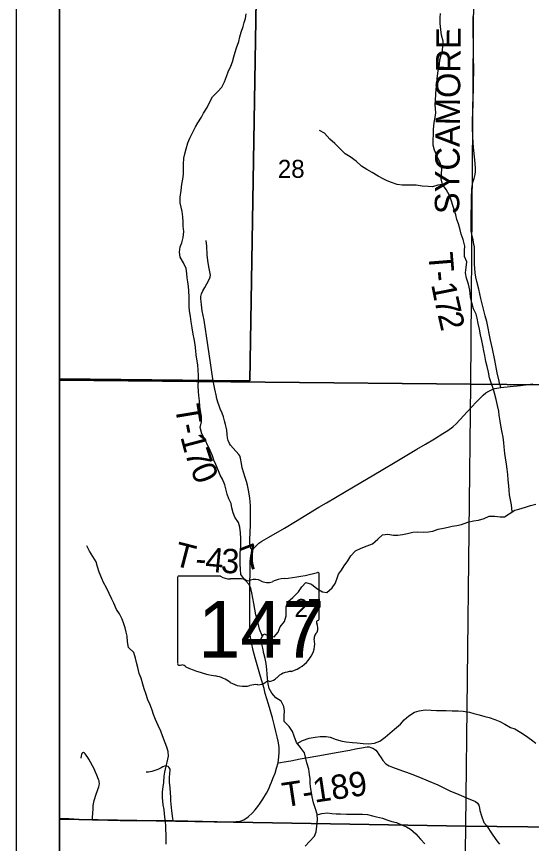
# Model space of a CAD drawing. Extents: x 0 to 34, y -8.9 to 22.
# Drawn here: x 23.617 to 24.815, y 8.187 to 10.111 of the extents above; entities that cross this region are included whole.
import ezdxf

# ---------------------------------------------------------------- set-up
doc = ezdxf.new("R2010")
doc.units = 0
for name, color, linetype in [('GM_X_Corporation', 7, 'Continuous'), ('GM_X_Minor_River', 7, 'Continuous'), ('GM_X_Section_Text', 7, 'Continuous'), ('GM_X_State_Location', 7, 'Continuous'), ('GM_X_State_Route', 7, 'Continuous'), ('GM_X_State_Shield', 7, 'Continuous'), ('GM_X_Township_Road', 7, 'Continuous'), ('GM_X_Township_Road_Text', 7, 'Continuous'), ('SH_Data', 7, 'Continuous')]:
    doc.layers.add(name, color=color, linetype=linetype)

msp = doc.modelspace()

# ---------------------------------------------------------------- linework, layer by layer
at = {"layer": 'GM_X_Corporation'}
for points in [[(23.7167, 11.9654), (23.7167, 7.104), (28.7046, 7.104), (28.7123, 8.2818), (28.7238, 9.1729), (28.7308, 9.4444), (28.7377, 10.2012)], [(24.1844, 10.755), (24.1596, 9.2636), (24.0743, 9.2644), (23.7167, 9.2682), (23.7167, 7.104), (28.7046, 7.104), (28.7123, 8.2818), (28.7238, 9.1729), (28.7308, 9.4444), (28.7377, 10.2012)]]:
    msp.add_lwpolyline(points, dxfattribs=at)
for points in [[(23.7167, 11.9654), (23.7167, 9.2682), (24.0743, 9.2644), (24.1596, 9.2636), (24.1844, 10.755), (24.1845, 10.7587), (24.2007, 11.7362), (24.2025, 11.824), (24.2028, 11.8378), (24.2054, 11.9625), (24.1849, 11.9621)], [(23.7167, 10.2843), (23.7167, 9.2652), (24.6733, 9.2562), (24.6816, 10.2678)], [(24.6816, 10.2678), (25.698, 10.2614), (25.683, 9.2467), (24.6733, 9.2562)], [(23.7167, 9.2652), (23.7167, 8.2443), (24.6618, 8.2279), (24.6733, 9.2562)], [(25.683, 9.2467), (25.6692, 8.2169), (24.6618, 8.2279), (24.6733, 9.2562)], [(23.7167, 8.2443), (23.7167, 7.2154), (24.6491, 7.2004), (24.6618, 8.2279)], [(24.6618, 8.2279), (25.6692, 8.2169), (25.6523, 7.1969), (24.6491, 7.2004)]]:
    msp.add_lwpolyline(points, close=True, dxfattribs=at)
at = {"layer": 'GM_X_Minor_River'}
for points in [[(24.0515, 9.8863), (24.0602, 9.9), (24.067, 9.9141), (24.0723, 9.9244), (24.0852, 9.937), (24.0942, 9.9473), (24.1003, 9.959), (24.1048, 9.972), (24.109, 9.9826), (24.1154, 9.9956), (24.1191, 10.0062), (24.1222, 10.0176), (24.1252, 10.0283), (24.1286, 10.0381), (24.1335, 10.053), (24.1361, 10.064), (24.1391, 10.0746), (24.1436, 10.0879), (24.1466, 10.0975), (24.1493, 10.107), (24.1511, 10.1172)], [(24.7698, 8.9588), (24.7678, 8.9756), (24.7658, 8.9866), (24.7639, 8.9983), (24.7628, 9.0094), (24.762, 9.0196), (24.7608, 9.0336), (24.7596, 9.0458), (24.7581, 9.0579), (24.7569, 9.0697), (24.7542, 9.0849), (24.7527, 9.0947), (24.7508, 9.1099), (24.7504, 9.1198), (24.7488, 9.1327), (24.7461, 9.1433), (24.7434, 9.16), (24.7419, 9.1699), (24.7396, 9.1835), (24.7384, 9.1934), (24.7357, 9.2067), (24.7323, 9.2207), (24.7285, 9.2348), (24.7254, 9.2461), (24.7208, 9.2594), (24.717, 9.2704), (24.7143, 9.2841), (24.7116, 9.2974), (24.7086, 9.3087), (24.7063, 9.3224), (24.704, 9.3338), (24.7013, 9.3463), (24.6993, 9.3577), (24.6963, 9.371), (24.6936, 9.3839), (24.6909, 9.3971), (24.6886, 9.4097), (24.6859, 9.4191), (24.6798, 9.4313), (24.6756, 9.4449), (24.6729, 9.4593), (24.671, 9.4745), (24.6683, 9.4886), (24.6637, 9.5022), (24.6614, 9.5147), (24.6629, 9.5277), (24.6644, 9.5406), (24.659, 9.5531), (24.659, 9.5671), (24.6597, 9.5774), (24.6559, 9.5926), (24.6513, 9.6051), (24.6487, 9.615), (24.6445, 9.629), (24.641, 9.6392), (24.6383, 9.6499), (24.6353, 9.6597), (24.6314, 9.6719), (24.6284, 9.6821), (24.6238, 9.6946), (24.6162, 9.7086), (24.6078, 9.7204), (24.6047, 9.7333), (24.6055, 9.7451), (24.6058, 9.7572), (24.6024, 9.7709), (24.5951, 9.786), (24.589, 9.8001), (24.5863, 9.8122), (24.5859, 9.8228), (24.5867, 9.838), (24.587, 9.8487), (24.5885, 9.8646), (24.5907, 9.8764), (24.5919, 9.887), (24.5914, 9.8965), (24.5907, 9.9068), (24.591, 9.917), (24.5921, 9.9307), (24.5929, 9.9425), (24.5947, 9.9546), (24.5955, 9.9664), (24.5969, 9.9797), (24.5984, 9.9896), (24.6003, 9.9999), (24.6018, 10.0109), (24.6044, 10.0219), (24.6074, 10.0314), (24.6086, 10.0436), (24.6093, 10.0538), (24.6055, 10.0682), (24.6035, 10.0811), (24.602, 10.0948), (24.6019, 10.1089), (24.6031, 10.1184)], [(24.1887, 8.6691), (24.1818, 8.6862), (24.1787, 8.6998), (24.1764, 8.7093), (24.1737, 8.7196), (24.1707, 8.7325), (24.1684, 8.7457), (24.1664, 8.7583), (24.1637, 8.7704), (24.1614, 8.7803), (24.1576, 8.7897), (24.1477, 8.8011), (24.1382, 8.8132), (24.1374, 8.8254), (24.137, 8.8371), (24.1366, 8.8508), (24.137, 8.8637), (24.1381, 8.877), (24.1384, 8.8876), (24.1384, 8.8971), (24.138, 8.9104), (24.1361, 8.9233), (24.133, 8.9343), (24.1246, 8.9468), (24.1204, 8.9567), (24.1178, 8.9684), (24.1158, 8.9787), (24.1109, 8.9889), (24.1063, 9.0003), (24.1036, 9.0124), (24.1009, 9.0219), (24.0956, 9.0348), (24.0903, 9.0446), (24.0868, 9.0545), (24.0807, 9.0689), (24.0754, 9.0791), (24.0723, 9.0894), (24.067, 9.1019), (24.059, 9.1178), (24.0548, 9.1273), (24.0476, 9.1402), (24.0441, 9.1554), (24.0467, 9.1687), (24.0467, 9.1819), (24.0448, 9.1941), (24.0432, 9.2043), (24.0424, 9.2169), (24.0409, 9.2298), (24.0397, 9.2392), (24.039, 9.2518), (24.0397, 9.2639), (24.04, 9.2753), (24.0392, 9.2894), (24.0381, 9.3), (24.0346, 9.3239), (24.0335, 9.3334), (24.0319, 9.3482), (24.03, 9.3611), (24.0277, 9.3725), (24.0254, 9.3869), (24.0231, 9.4009), (24.0211, 9.4135), (24.0188, 9.4267), (24.018, 9.4366), (24.0184, 9.448), (24.018, 9.4586), (24.0176, 9.4734), (24.0164, 9.4829), (24.0149, 9.4939), (24.0133, 9.5034), (24.0125, 9.5137), (24.011, 9.5251), (24.0049, 9.538), (23.9977, 9.5516), (23.9961, 9.563), (23.9972, 9.5751), (24.001, 9.585), (24.004, 9.5972), (24.0059, 9.6109), (24.0043, 9.6238), (24.0043, 9.634), (24.0039, 9.645), (24.0023, 9.6576), (23.9997, 9.6674), (23.9977, 9.6781), (23.9973, 9.691), (24, 9.7062), (24.0014, 9.721), (24.0033, 9.7328), (24.0052, 9.7445), (24.0051, 9.7681), (24.0062, 9.7821), (24.0085, 9.7916), (24.0111, 9.8038), (24.0149, 9.8171), (24.0202, 9.8285), (24.0273, 9.8441), (24.033, 9.8544), (24.0387, 9.8639), (24.047, 9.8768), (24.0515, 9.8863)], [(24.6078, 9.7204), (24.5968, 9.7192), (24.5847, 9.7154), (24.5744, 9.7161), (24.56, 9.7168), (24.5463, 9.7187), (24.5334, 9.719), (24.5236, 9.7186), (24.5141, 9.7193), (24.5019, 9.7208), (24.489, 9.7249), (24.4791, 9.7291), (24.4693, 9.734), (24.4579, 9.74), (24.4438, 9.7483), (24.432, 9.7551), (24.4191, 9.7634), (24.4066, 9.7751), (24.3929, 9.7846), (24.3815, 9.7921), (24.3697, 9.8035), (24.3568, 9.8156), (24.3457, 9.8262), (24.3332, 9.8402), (24.3214, 9.8459)], [(24.2163, 8.6685), (24.225, 8.6791), (24.2299, 8.6917), (24.2402, 8.7039), (24.2443, 8.7168), (24.2443, 8.7377), (24.248, 8.7498), (24.2598, 8.7593), (24.273, 8.7727), (24.2802, 8.7845), (24.29, 8.7944), (24.303, 8.7906), (24.3155, 8.7804), (24.3284, 8.7729), (24.3383, 8.7714), (24.3508, 8.7821), (24.3576, 8.792), (24.3621, 8.8022), (24.3655, 8.8136), (24.3727, 8.8235), (24.3788, 8.833), (24.3871, 8.8452), (24.3943, 8.857), (24.4052, 8.8684), (24.4181, 8.8745), (24.4322, 8.8799), (24.4447, 8.8849), (24.4572, 8.8952), (24.4681, 8.9051), (24.4807, 8.9074), (24.494, 8.9044), (24.5038, 8.9048), (24.5148, 8.9064), (24.5262, 8.9083), (24.5387, 8.9118), (24.5505, 8.9122), (24.5641, 8.9115), (24.5748, 8.9123), (24.585, 8.9142), (24.5975, 8.9184), (24.61, 8.9211), (24.621, 8.9231), (24.6305, 8.9254), (24.6411, 8.9273), (24.6518, 8.9296), (24.6665, 8.935), (24.6798, 8.9381), (24.6916, 8.9396), (24.7045, 8.9435), (24.7162, 8.9492), (24.7291, 8.9489), (24.742, 8.947), (24.7519, 8.9474), (24.7625, 8.9543), (24.7761, 8.9627), (24.7856, 8.9654), (24.8004, 8.9696), (24.8125, 8.9738), (24.8251, 8.9769)], [(23.9647, 8.1855), (23.9646, 8.2094), (23.9642, 8.2193), (23.9642, 8.2299), (23.9627, 8.2424), (23.9607, 8.2561), (23.9603, 8.2663), (23.958, 8.2773), (23.9565, 8.2944), (23.9565, 8.3077), (23.9579, 8.3191), (23.9591, 8.329), (23.9605, 8.3438), (23.962, 8.3533), (23.9647, 8.3673), (23.9669, 8.3768), (23.9699, 8.3905), (23.9695, 8.4015), (23.9665, 8.4117), (23.9623, 8.4212), (23.9562, 8.4375), (23.9523, 8.4485), (23.9462, 8.4622), (23.9398, 8.4758), (23.9356, 8.4872), (23.9325, 8.4974), (23.9272, 8.5103), (23.9222, 8.5217), (23.9176, 8.5361), (23.9138, 8.5471), (23.9107, 8.5577), (23.9069, 8.5717), (23.9016, 8.5831), (23.8985, 8.5968), (23.8958, 8.6085), (23.8935, 8.6188), (23.8893, 8.632), (23.8768, 8.6434), (23.8745, 8.6567), (23.8741, 8.6696), (23.8721, 8.6794), (23.8695, 8.6889), (23.8664, 8.6984), (23.8626, 8.7094), (23.8565, 8.7219), (23.8489, 8.7321), (23.8432, 8.7462), (23.8382, 8.7556), (23.8325, 8.7689), (23.826, 8.7818), (23.8191, 8.7947), (23.815, 8.8042), (23.8089, 8.8186), (23.805, 8.8307), (23.8016, 8.8428), (23.7943, 8.855), (23.7867, 8.8675), (23.7799, 8.88)], [(24.288, 8.1813), (24.2986, 8.1919), (24.31, 8.2045), (24.3141, 8.2148), (24.3156, 8.2277), (24.3171, 8.2421), (24.3159, 8.2554), (24.3121, 8.2679), (24.3075, 8.2823), (24.3048, 8.2956), (24.3025, 8.3062), (24.3006, 8.3191), (24.2998, 8.3286), (24.2994, 8.3381), (24.2986, 8.3476), (24.2963, 8.3605), (24.2921, 8.3749), (24.2894, 8.3851), (24.2864, 8.3984), (24.2772, 8.4109), (24.2677, 8.4223), (24.2628, 8.4374), (24.259, 8.4477), (24.2513, 8.4598), (24.2395, 8.4715), (24.2395, 8.484), (24.2399, 8.4962), (24.2387, 8.5064), (24.2326, 8.5182), (24.2201, 8.5265), (24.2109, 8.5371), (24.2045, 8.5481), (24.2018, 8.5591), (24.2002, 8.5716), (24.1995, 8.5811), (24.1987, 8.5921), (24.1971, 8.6058), (24.1952, 8.6175), (24.1921, 8.6297), (24.1895, 8.6418), (24.1872, 8.6513), (24.186, 8.6642), (24.192, 8.6752), (24.2046, 8.6703), (24.2163, 8.6685)], [(24.2696, 8.42), (24.2821, 8.4272), (24.2973, 8.4326), (24.3117, 8.4349), (24.3227, 8.4361), (24.3368, 8.4362), (24.3463, 8.4347), (24.3603, 8.4294), (24.3744, 8.4253), (24.3838, 8.4238), (24.3986, 8.4223), (24.4093, 8.4212), (24.4233, 8.4198), (24.4362, 8.4194), (24.4491, 8.421), (24.462, 8.4252), (24.4745, 8.4344), (24.4851, 8.4443), (24.4957, 8.453), (24.5097, 8.4652), (24.5181, 8.4747), (24.529, 8.4847), (24.5423, 8.4931), (24.5537, 8.4961), (24.5673, 8.4981), (24.581, 8.4977), (24.5939, 8.497), (24.6049, 8.4967), (24.6159, 8.4967), (24.63, 8.4964), (24.644, 8.4961), (24.6558, 8.495), (24.6702, 8.4927), (24.6808, 8.4901), (24.6926, 8.4864), (24.7063, 8.4826), (24.7161, 8.4804), (24.7294, 8.4755), (24.7412, 8.471), (24.753, 8.4653), (24.7655, 8.457), (24.7761, 8.454), (24.7902, 8.4453), (24.8008, 8.4385), (24.8145, 8.4287), (24.8248, 8.4211)], [(24.3161, 8.2538), (24.3269, 8.2573), (24.3398, 8.2585), (24.3504, 8.2574), (24.3599, 8.2567), (24.3702, 8.2563), (24.3842, 8.2556), (24.3952, 8.2553), (24.4085, 8.2557), (24.4218, 8.2558), (24.4328, 8.2547), (24.4446, 8.2517), (24.4544, 8.2498), (24.4677, 8.2464), (24.478, 8.2427), (24.4897, 8.2389), (24.5008, 8.2359), (24.5106, 8.2318), (24.5239, 8.2265), (24.5334, 8.2205), (24.546, 8.2099), (24.5562, 8.1978), (24.5665, 8.1868)]]:
    msp.add_lwpolyline(points, dxfattribs=at)
at = {"layer": 'GM_X_State_Route'}
for points in [[(23.784, 8.2432), (23.7935, 8.2426), (23.8063, 8.2423), (23.8292, 8.2416), (23.8577, 8.2412), (23.8961, 8.2409), (23.9255, 8.2409), (23.9612, 8.2407), (23.9808, 8.2406), (24.0833, 8.2385), (24.1176, 8.2378), (24.128, 8.2386), (24.1369, 8.2396), (24.1456, 8.2428), (24.1557, 8.2494), (24.1659, 8.2589), (24.1716, 8.2656), (24.1781, 8.2738), (24.1837, 8.2816), (24.19, 8.2907), (24.1983, 8.3046), (24.2034, 8.3148), (24.2069, 8.3229), (24.21, 8.3299), (24.2133, 8.3388), (24.2181, 8.3511), (24.2217, 8.3623), (24.2252, 8.3751), (24.2265, 8.3892), (24.2274, 8.3987), (24.2273, 8.4096), (24.2267, 8.4169), (24.2254, 8.4254), (24.2232, 8.4357), (24.2199, 8.4481), (24.2168, 8.461), (24.2118, 8.4797), (24.2025, 8.5118), (24.1953, 8.5367), (24.1924, 8.5481), (24.184, 8.5756), (24.1719, 8.6195), (24.1674, 8.6365), (24.163, 8.6551), (24.1608, 8.6668), (24.1601, 8.6742), (24.1595, 8.6878), (24.1591, 8.6994), (24.1591, 8.721), (24.1598, 8.7806), (24.1601, 8.8297), (24.1604, 8.8443), (24.1609, 8.85), (24.1619, 8.857), (24.163, 8.8621), (24.1659, 8.8695), (24.1691, 8.8746), (24.1757, 8.8816), (24.1805, 8.8858), (24.1875, 8.8908), (24.2034, 8.9004), (24.2398, 8.9213), (24.2655, 8.9368), (24.3202, 8.9696), (24.338, 8.9801), (24.4007, 9.017), (24.4646, 9.055), (24.5015, 9.0771), (24.5477, 9.1044), (24.5681, 9.1165), (24.5887, 9.1286), (24.6085, 9.1409), (24.6202, 9.1484), (24.6314, 9.1565), (24.6402, 9.1644), (24.6567, 9.1824), (24.676, 9.2036), (24.6861, 9.2142), (24.7025, 9.2305), (24.7088, 9.2355), (24.7156, 9.2398), (24.7232, 9.2438), (24.7297, 9.2456), (24.7434, 9.2485), (24.7647, 9.2505), (24.7888, 9.2532), (24.8178, 9.2564)], [(23.7167, 8.2467), (23.7385, 8.2457), (23.7622, 8.2443), (23.7803, 8.2435), (23.784, 8.2432)]]:
    msp.add_lwpolyline(points, dxfattribs=at)
at = {"layer": 'GM_X_State_Shield'}
for p, q in [((24.3208, 8.7096), (24.3208, 8.8143)), ((23.9912, 8.8059), (23.9912, 8.6058)), ((24.091, 8.8093), (23.9945, 8.8093)), ((24.3208, 8.7096), (24.3208, 8.7096))]:
    msp.add_line(p, q, dxfattribs=at)
for centre, major_axis, start_param, end_param in [((24.2034, 9.0822), (0.3495, 0), 4.814394, 5.042369), ((24.3172, 8.8147), (0.00367, 0), 6.141152, 7.989035), ((23.995, 8.8063), (0.00382, 0), 1.712693, 3.28349), ((24.114, 8.8326), (0.037, 0), 4.042523, 4.731795), ((24.1263, 8.697), (0.133, 0), 1.404758, 1.657858), ((24.1564, 8.8073), (0.0107, 0), 3.836095, 5.185415), ((24.1721, 8.7842), (0.0222, 0), 0.950623, 2.079405), ((24.2008, 8.8159), (0.0267, 0), 4.081561, 5.145723), ((24.248, 8.7482), (0.0703, 0), 1.699011, 2.107814), ((24.32, 8.7019), (0.00568, 0), 1.883978, 3.671073), ((24.2838, 8.6887), (0.0341, 0), 5.934695, 6.695948), ((24.3169, 8.7092), (0.00393, 0), 5.05454, 6.418171), ((24.334, 8.6658), (0.0248, 0), 2.387724, 3.262537), ((24.223, 8.6525), (0.0874, 0), 5.101752, 6.440018), ((23.995, 8.6053), (0.00385, 0), 3.00124, 4.508301), ((23.9956, 8.6258), (0.0294, 0), 4.665946, 4.897461), ((24.0016, 8.5942), (0.0106, 0), 0.519207, 1.627899), ((24.1355, 8.774), (0.2524, 0), 4.195997, 4.488961), ((24.2599, 8.5496), (0.0479, 0), 1.647645, 2.488434), ((24.0602, 8.5159), (0.079, 0), 0.823519, 1.323587), ((24.1456, 8.5932), (0.0501, 0), 4.026481, 4.996735), ((24.1782, 8.5782), (0.0267, 0), 4.691044, 5.507374), ((24.2024, 8.5589), (0.00752, 0), 1.147584, 2.315152), ((24.1992, 8.5864), (0.0282, 0), 4.937069, 5.64225), ((24.1746, 8.524), (0.0412, 0), 1.495662, 1.94098)]:
    msp.add_ellipse(centre, major_axis=major_axis, ratio=0.8, start_param=start_param, end_param=end_param, dxfattribs=at)
at = {"layer": 'GM_X_Township_Road'}
for points in [[(24.7434, 9.2485), (24.7415, 9.2539), (24.7403, 9.2578), (24.7391, 9.2632), (24.7351, 9.2825), (24.7294, 9.3121), (24.724, 9.3385), (24.7197, 9.3587), (24.7106, 9.4017), (24.7069, 9.4153), (24.697, 9.4549), (24.6918, 9.4772), (24.6873, 9.4946), (24.6851, 9.5051), (24.6835, 9.5147), (24.6823, 9.5349), (24.6822, 9.5589), (24.6818, 9.5708), (24.6818, 9.5756), (24.6807, 9.5806), (24.6789, 9.5915), (24.6767, 9.6005), (24.6745, 9.6126), (24.6743, 9.6221), (24.6743, 9.6338), (24.6742, 9.6527), (24.675, 9.6712), (24.6755, 9.695), (24.6757, 9.7042), (24.6762, 9.7106), (24.6768, 9.7163), (24.6777, 9.7216), (24.6792, 9.7284), (24.6812, 9.7346), (24.684, 9.7437), (24.6846, 9.7509), (24.6847, 9.7575), (24.684, 9.7695), (24.6832, 9.7775), (24.6801, 9.8064), (24.6779, 9.8306), (24.6776, 9.8541), (24.6774, 9.8699), (24.679, 9.9065), (24.6798, 9.9573), (24.6803, 9.9865), (24.6801, 10.018), (24.6795, 10.0496), (24.6789, 10.0718), (24.6789, 10.0835), (24.6788, 10.0987), (24.6793, 10.1082), (24.6799, 10.116)], [(24.0815, 9.2274), (24.0777, 9.2446), (24.0745, 9.2638), (24.0714, 9.2839), (24.0678, 9.3058), (24.0649, 9.3268), (24.062, 9.3477), (24.0531, 9.4048), (24.0488, 9.4266), (24.0466, 9.4407), (24.046, 9.4483), (24.0456, 9.4543), (24.0458, 9.4596), (24.0464, 9.4633), (24.0472, 9.4663), (24.0504, 9.4728), (24.0547, 9.4807), (24.0644, 9.498), (24.0665, 9.5033), (24.0672, 9.5059), (24.0677, 9.5094), (24.0644, 9.5289), (24.062, 9.544), (24.0603, 9.5571), (24.0594, 9.5773), (24.0582, 9.5899)], [(24.1659, 8.8695), (24.162, 8.8737), (24.1605, 8.8803), (24.1596, 8.886), (24.1595, 8.8949), (24.1606, 8.9282), (24.1609, 8.9496), (24.1609, 8.9726), (24.1592, 8.9919), (24.1565, 9.0094), (24.1542, 9.0209), (24.1515, 9.0297), (24.1477, 9.0411), (24.1453, 9.0488), (24.1417, 9.0615), (24.14, 9.0716), (24.1378, 9.0838), (24.1359, 9.0892), (24.134, 9.0927), (24.1205, 9.1071), (24.1148, 9.1138), (24.112, 9.1183), (24.1089, 9.125), (24.1075, 9.1313), (24.1064, 9.1386), (24.1056, 9.1488), (24.1042, 9.1559), (24.103, 9.1621), (24.1005, 9.1708), (24.0979, 9.1798), (24.0947, 9.1887), (24.0904, 9.1985), (24.0878, 9.2052), (24.0846, 9.2142), (24.0819, 9.2253), (24.0815, 9.2274)], [(24.2252, 8.3751), (24.2308, 8.3758), (24.2391, 8.3771), (24.2546, 8.3799), (24.2767, 8.3844), (24.295, 8.3878), (24.3178, 8.3915), (24.3391, 8.3952), (24.3601, 8.399), (24.3923, 8.4049), (24.4051, 8.4073), (24.419, 8.4103), (24.4327, 8.412), (24.4368, 8.412), (24.4413, 8.4108), (24.4454, 8.4095), (24.4495, 8.4071), (24.4527, 8.4045), (24.4559, 8.4004), (24.4595, 8.3946), (24.4649, 8.3863), (24.4691, 8.3801), (24.4762, 8.3729), (24.4837, 8.3683), (24.4913, 8.365), (24.4977, 8.3624), (24.5081, 8.3587), (24.5148, 8.3563), (24.5241, 8.353), (24.5361, 8.3488), (24.5543, 8.3418), (24.5743, 8.3332), (24.5969, 8.3235), (24.6246, 8.3102), (24.6454, 8.3013), (24.6689, 8.2916), (24.6791, 8.2875), (24.6843, 8.2853), (24.6889, 8.2814), (24.6921, 8.2763), (24.6934, 8.2699), (24.6942, 8.264), (24.698, 8.2514), (24.7041, 8.2364), (24.71, 8.2296), (24.7233, 8.2088), (24.73, 8.1989), (24.736, 8.1907), (24.7402, 8.1858)], [(23.7935, 8.2426), (23.7934, 8.2474), (23.7942, 8.2589), (23.7946, 8.2672), (23.7952, 8.2759), (23.7972, 8.2875), (23.8021, 8.3023), (23.805, 8.3106), (23.8067, 8.3153), (23.8081, 8.3192), (23.8088, 8.3227), (23.8094, 8.3269), (23.8092, 8.3297), (23.8087, 8.3333), (23.8077, 8.336), (23.8031, 8.3465), (23.8004, 8.3533), (23.7972, 8.361), (23.7933, 8.3679), (23.7886, 8.3764), (23.7848, 8.3833), (23.7824, 8.3876), (23.779, 8.393), (23.7764, 8.3961), (23.7747, 8.3979), (23.7724, 8.3988), (23.7702, 8.3983), (23.7688, 8.3971), (23.768, 8.3947), (23.7672, 8.391), (23.7666, 8.3862)], [(23.9808, 8.2406), (23.98, 8.2457), (23.9778, 8.2632), (23.9759, 8.2869), (23.9753, 8.2943), (23.9741, 8.3165), (23.9729, 8.3302), (23.9727, 8.3392), (23.9735, 8.3516), (23.9737, 8.3562), (23.9739, 8.3601), (23.9728, 8.3628), (23.971, 8.3649), (23.9691, 8.3664), (23.9667, 8.3674), (23.9648, 8.3677), (23.9608, 8.3671), (23.9568, 8.3657), (23.9528, 8.3637), (23.945, 8.3599), (23.9384, 8.3571), (23.9315, 8.3548), (23.9239, 8.3532), (23.9183, 8.353)]]:
    msp.add_lwpolyline(points, dxfattribs=at)
at = {"layer": 'SH_Data'}
for points in [[(23.6167, 14.004), (30.6167, 14.004), (30.6167, 7.004), (23.6167, 7.004)], [(23.7167, 13.904), (30.5167, 13.904), (30.5167, 7.104), (23.7167, 7.104)]]:
    msp.add_lwpolyline(points, close=True, dxfattribs=at)

# ---------------------------------------------------------------- texts
at = {"layer": 'GM_X_Section_Text'}
for s, p in [('28', (24.2246, 9.736)), ('27', (24.2634, 8.7143))]:
    msp.add_text(s, height=0.04186, rotation=0, dxfattribs=at).set_placement(p)
at = {"layer": 'GM_X_State_Location'}
msp.add_text('147', height=0.000189, rotation=0, dxfattribs=at).set_placement((24.0855, 8.6787))
for s in ['s', 'r']:
    msp.add_text(s, height=0.000189, dxfattribs=at).set_placement((24.1523, 8.6925))
at = {"layer": 'GM_X_State_Shield'}
msp.add_text('147', height=0.13184, dxfattribs=at).set_placement((24.0391, 8.6199))
at = {"layer": 'GM_X_Township_Road_Text'}
for s, height, rotation, p in [('SYCAMORE', 0.05682, 89.5094, (24.6464, 9.6513)), ('T', 0.0568, 274.6291, (24.5746, 9.5607)), ('-', 0.0568, 275.0175, (24.5781, 9.5179)), ('1', 0.0568, 281.1453, (24.5811, 9.4881)), ('7', 0.0568, 282.8759, (24.5882, 9.452)), ('2', 0.0568, 282.9556, (24.5961, 9.4178)), ('T', 0.0568, 279.406, (23.9848, 9.2043)), ('-', 0.0568, 281.049, (23.9921, 9.1606)), ('1', 0.0568, 284.8367, (23.9974, 9.1337)), ('7', 0.0568, 288.2626, (24.0075, 9.0963)), ('0', 0.0568, 292.5189, (24.02, 9.0588)), ('T', 0.0568, 345.4482, (23.9793, 8.835)), ('4', 0.0568, 354.6845, (24.0542, 8.8207)), ('3', 0.0568, 356.7672, (24.0913, 8.8173)), ('7', 0.0568, 20.9784, (24.152, 8.8193)), ('-', 0.0568, 355.5557, (24.0312, 8.8225)), ('T-189', 0.05682, 8.4483, (24.2391, 8.2717))]:
    msp.add_text(s, height=height, rotation=rotation, dxfattribs=at).set_placement(p)

doc.saveas('drawing.dxf')
